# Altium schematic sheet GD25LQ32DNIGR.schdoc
size 127 x 101 mm
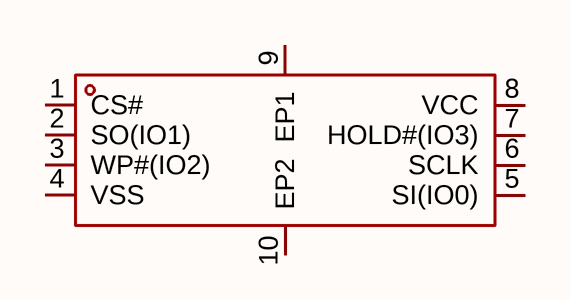
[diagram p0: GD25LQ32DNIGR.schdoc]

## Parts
U?  gd25lq32dnigr  [USON-8_L4.0-W3.0-P0.80-BL_GD25Q32CNIGR]  (value not drawn)

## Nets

Not connected (* = marked no-connect by the designer): U? 1(CS#) 2(SO(IO1)) 3(WP#(IO2)) 4(VSS) 5(SI(IO0)) 6(SCLK) 7(HOLD#(IO3)) 8(VCC) 9(EP1) 10(EP2)

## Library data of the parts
U? = gd25lq32dnigr: 接口类型:SPI;存储容量:32Mbit;; Manufacturer: GigaDevice(兆易创新); AddInBom: yes; ModelId: ce39ad9f02d04d848d7f2c3c3cc09f44; ModelName: USON-8_L4.0-W3.0-H0.6-P0.80-BL_GD25Q32CNIGR; ModelTransform: 118.8974,158.267,0,90,0,0,-0.002,0.002,0; Interface: SPI; Memory Size: 32Mbit; Voltage - Supply: 1.65V~2V; Page Programming Time (Tpp): 2.4ms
